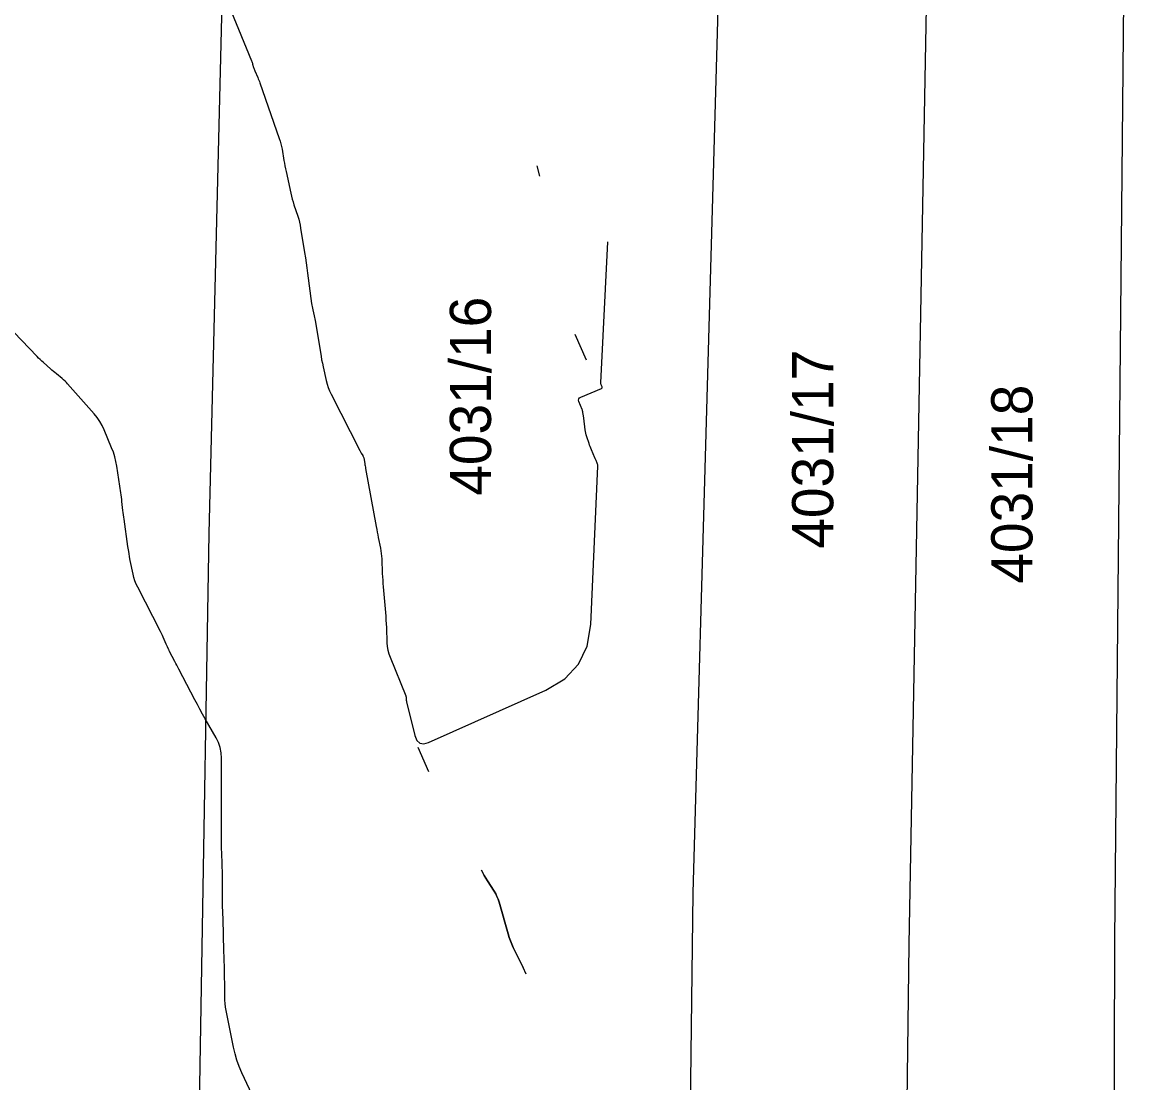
# Model space of a CAD drawing. Extents: x -534410 to -534262, y -1190162 to -1189584.
# Drawn here: x -534348.63 to -534325.54, y -1189747.77 to -1189725.88 of the extents above; entities that cross this region are included whole.
import ezdxf

# ---------------------------------------------------------------- set-up
doc = ezdxf.new("R2010")
doc.units = 0
for name, color, linetype in [('30', 7, 'Continuous'), ('31', 7, 'Continuous'), ('Hranice parcel', 7, 'Continuous'), ('Parcelní čísla', 7, 'Continuous')]:
    doc.layers.add(name, color=color, linetype=linetype)

msp = doc.modelspace()

# ---------------------------------------------------------------- linework, layer by layer
at = {"layer": '30'}
for points in [[(-534338.004, -1189728.845), (-534337.953, -1189729.054)], [(-534343.782, -1189748.239), (-534344.094, -1189747.565), (-534344.149, -1189747.437), (-534344.196, -1189747.307), (-534344.235, -1189747.175), (-534344.266, -1189747.039), (-534344.42, -1189746.283), (-534344.433, -1189746.21), (-534344.442, -1189746.138), (-534344.447, -1189746.065), (-534344.449, -1189745.992), (-534344.449, -1189745.698), (-534344.45, -1189745.624), (-534344.45, -1189745.551), (-534344.452, -1189745.477), (-534344.454, -1189745.404), (-534344.467, -1189745.021), (-534344.469, -1189744.933), (-534344.472, -1189744.844), (-534344.475, -1189744.756), (-534344.477, -1189744.668), (-534344.49, -1189744.219), (-534344.492, -1189744.156), (-534344.493, -1189744.094), (-534344.493, -1189744.032), (-534344.494, -1189743.969), (-534344.494, -1189743.72), (-534344.494, -1189743.657), (-534344.495, -1189743.595), (-534344.496, -1189743.533), (-534344.497, -1189743.47), (-534344.51, -1189743.032), (-534344.513, -1189742.938), (-534344.515, -1189742.844), (-534344.516, -1189742.751), (-534344.516, -1189742.657), (-534344.516, -1189741.069), (-534344.523, -1189740.959), (-534344.544, -1189740.852), (-534344.579, -1189740.749), (-534344.628, -1189740.649), (-534344.851, -1189740.259), (-534344.906, -1189740.161), (-534344.96, -1189740.063), (-534345.013, -1189739.964), (-534345.066, -1189739.864), (-534345.394, -1189739.231), (-534345.414, -1189739.192), (-534345.435, -1189739.153), (-534345.455, -1189739.115), (-534345.476, -1189739.076), (-534345.587, -1189738.868), (-534345.593, -1189738.856), (-534345.599, -1189738.844), (-534345.605, -1189738.832), (-534345.611, -1189738.82), (-534345.633, -1189738.771), (-534345.639, -1189738.758), (-534345.644, -1189738.746), (-534345.65, -1189738.734), (-534345.655, -1189738.721), (-534345.718, -1189738.571), (-534345.731, -1189738.542), (-534345.744, -1189738.513), (-534345.758, -1189738.485), (-534345.772, -1189738.457), (-534346.245, -1189737.541), (-534346.276, -1189737.476), (-534346.302, -1189737.409), (-534346.323, -1189737.341), (-534346.34, -1189737.271), (-534346.399, -1189736.987), (-534346.413, -1189736.915), (-534346.425, -1189736.844), (-534346.437, -1189736.773), (-534346.448, -1189736.701), (-534346.527, -1189736.139), (-534346.533, -1189736.094), (-534346.539, -1189736.048), (-534346.545, -1189736.002), (-534346.55, -1189735.957), (-534346.571, -1189735.774), (-534346.576, -1189735.728), (-534346.582, -1189735.683), (-534346.588, -1189735.637), (-534346.595, -1189735.591), (-534346.677, -1189735.041), (-534346.695, -1189734.943), (-534346.718, -1189734.848), (-534346.747, -1189734.754), (-534346.783, -1189734.661), (-534346.935, -1189734.295), (-534346.976, -1189734.206), (-534347.024, -1189734.121), (-534347.08, -1189734.04), (-534347.142, -1189733.963), (-534347.692, -1189733.341), (-534347.718, -1189733.312), (-534347.745, -1189733.285), (-534347.774, -1189733.259), (-534347.804, -1189733.234), (-534347.925, -1189733.136), (-534347.956, -1189733.112), (-534347.985, -1189733.087), (-534348.015, -1189733.061), (-534348.044, -1189733.036), (-534348.191, -1189732.905), (-534348.225, -1189732.875), (-534348.259, -1189732.843), (-534348.291, -1189732.811), (-534348.323, -1189732.778), (-534348.801, -1189732.273)], [(-534337.218, -1189732.319), (-534336.987, -1189732.845)]]:
    msp.add_lwpolyline(points, dxfattribs=at)
at = {"layer": '31'}
for points in [[(-534344.323, -1189725.638), (-534343.896, -1189726.672), (-534343.889, -1189726.689), (-534343.883, -1189726.706), (-534343.877, -1189726.723), (-534343.872, -1189726.74), (-534343.853, -1189726.81), (-534343.848, -1189726.827), (-534343.842, -1189726.844), (-534343.835, -1189726.861), (-534343.829, -1189726.878), (-534343.768, -1189727.016), (-534343.756, -1189727.044), (-534343.744, -1189727.073), (-534343.733, -1189727.102), (-534343.723, -1189727.131), (-534343.323, -1189728.277), (-534343.305, -1189728.332), (-534343.29, -1189728.388), (-534343.277, -1189728.444), (-534343.266, -1189728.501), (-534343.226, -1189728.73), (-534343.216, -1189728.787), (-534343.206, -1189728.844), (-534343.194, -1189728.901), (-534343.182, -1189728.958), (-534343.085, -1189729.408), (-534343.071, -1189729.468), (-534343.055, -1189729.529), (-534343.038, -1189729.588), (-534343.019, -1189729.648), (-534342.94, -1189729.884), (-534342.922, -1189729.944), (-534342.906, -1189730.004), (-534342.892, -1189730.064), (-534342.881, -1189730.126), (-534342.799, -1189730.634), (-534342.783, -1189730.739), (-534342.767, -1189730.845), (-534342.752, -1189730.95), (-534342.738, -1189731.056), (-534342.656, -1189731.685), (-534342.652, -1189731.717), (-534342.646, -1189731.749), (-534342.64, -1189731.781), (-534342.632, -1189731.813), (-534342.601, -1189731.939), (-534342.593, -1189731.971), (-534342.586, -1189732.003), (-534342.58, -1189732.035), (-534342.575, -1189732.067), (-534342.474, -1189732.698), (-534342.461, -1189732.771), (-534342.448, -1189732.844), (-534342.433, -1189732.917), (-534342.418, -1189732.989), (-534342.353, -1189733.277), (-534342.334, -1189733.349), (-534342.312, -1189733.418), (-534342.284, -1189733.487), (-534342.253, -1189733.553), (-534341.658, -1189734.721), (-534341.651, -1189734.733), (-534341.645, -1189734.746), (-534341.637, -1189734.759), (-534341.63, -1189734.771), (-534341.6, -1189734.82), (-534341.594, -1189734.832), (-534341.588, -1189734.845), (-534341.583, -1189734.859), (-534341.58, -1189734.873), (-534341.558, -1189734.991), (-534341.553, -1189735.015), (-534341.548, -1189735.039), (-534341.544, -1189735.064), (-534341.539, -1189735.088), (-534341.321, -1189736.291), (-534341.311, -1189736.347), (-534341.3, -1189736.402), (-534341.29, -1189736.457), (-534341.279, -1189736.513), (-534341.235, -1189736.734), (-534341.225, -1189736.789), (-534341.218, -1189736.845), (-534341.212, -1189736.901), (-534341.208, -1189736.957), (-534341.195, -1189737.26), (-534341.191, -1189737.33), (-534341.187, -1189737.399), (-534341.182, -1189737.468), (-534341.177, -1189737.537), (-534341.132, -1189738.064), (-534341.126, -1189738.142), (-534341.12, -1189738.22), (-534341.116, -1189738.298), (-534341.112, -1189738.376), (-534341.099, -1189738.688), (-534341.093, -1189738.766), (-534341.08, -1189738.842), (-534341.06, -1189738.916), (-534341.034, -1189738.989), (-534340.712, -1189739.786), (-534340.709, -1189739.796), (-534340.706, -1189739.806), (-534340.704, -1189739.816), (-534340.703, -1189739.826), (-534340.7, -1189739.868), (-534340.7, -1189739.878), (-534340.698, -1189739.888), (-534340.696, -1189739.898), (-534340.694, -1189739.909), (-534340.523, -1189740.605), (-534340.483, -1189740.704), (-534340.423, -1189740.76), (-534340.341, -1189740.773), (-534340.239, -1189740.745), (-534337.816, -1189739.668), (-534337.427, -1189739.436), (-534337.143, -1189739.132), (-534336.964, -1189738.757), (-534336.89, -1189738.311), (-534336.745, -1189735.042), (-534336.745, -1189735.027), (-534336.747, -1189735.012), (-534336.751, -1189734.998), (-534336.757, -1189734.984), (-534336.782, -1189734.929), (-534336.788, -1189734.915), (-534336.794, -1189734.901), (-534336.8, -1189734.888), (-534336.806, -1189734.874), (-534336.877, -1189734.706), (-534336.89, -1189734.673), (-534336.903, -1189734.64), (-534336.915, -1189734.607), (-534336.927, -1189734.573), (-534336.973, -1189734.434), (-534336.984, -1189734.399), (-534336.993, -1189734.364), (-534337, -1189734.329), (-534337.006, -1189734.293), (-534337.038, -1189734.055), (-534337.045, -1189734.004), (-534337.054, -1189733.936), (-534337.057, -1189733.919), (-534337.061, -1189733.903), (-534337.065, -1189733.887), (-534337.071, -1189733.87), (-534337.135, -1189733.711), (-534337.142, -1189733.681), (-534337.138, -1189733.656), (-534337.123, -1189733.635), (-534337.097, -1189733.62), (-534336.669, -1189733.438), (-534336.66, -1189733.432), (-534336.655, -1189733.426), (-534336.654, -1189733.417), (-534336.657, -1189733.408), (-534336.676, -1189733.365), (-534336.68, -1189733.355), (-534336.682, -1189733.344), (-534336.684, -1189733.333), (-534336.684, -1189733.321), (-534336.539, -1189730.411)], [(-534340.464, -1189740.845), (-534340.243, -1189741.344)], [(-534338.223, -1189745.528), (-534338.29, -1189745.392)]]:
    msp.add_lwpolyline(points, dxfattribs=at)
msp.add_lwpolyline([(-534338.491, -1189744.981), (-534338.523, -1189744.912), (-534338.551, -1189744.842), (-534338.577, -1189744.771), (-534338.599, -1189744.698), (-534338.785, -1189744.042), (-534338.804, -1189743.982), (-534338.828, -1189743.924), (-534338.855, -1189743.869), (-534338.887, -1189743.815), (-534339.023, -1189743.602), (-534339.057, -1189743.549), (-534339.089, -1189743.494), (-534339.119, -1189743.439), (-534339.148, -1189743.383), (-534339.119, -1189743.439), (-534339.089, -1189743.494), (-534339.057, -1189743.549), (-534339.023, -1189743.602), (-534338.887, -1189743.815), (-534338.855, -1189743.869), (-534338.828, -1189743.924), (-534338.804, -1189743.982), (-534338.785, -1189744.042), (-534338.599, -1189744.698), (-534338.577, -1189744.771), (-534338.551, -1189744.842), (-534338.523, -1189744.912), (-534338.491, -1189744.981), (-534338.29, -1189745.392)], close=True, dxfattribs=at)
at = {"layer": 'Hranice parcel'}
for points in [[(-534347.07, -1189935.15), (-534347.12, -1189900.1), (-534346.3, -1189826.77), (-534344.77, -1189736.43), (-534342.85, -1189658.07), (-534338.334, -1189584.47)], [(-534338.84, -1189942.48), (-534336.49, -1189881.83), (-534334.78, -1189743.85), (-534331.25, -1189619.05), (-534329.563, -1189584.47)], [(-534334.89, -1189942.46), (-534332.03, -1189880.06), (-534330.32, -1189744.92), (-534329.292, -1189689.47)], [(-534330.63, -1189942.43), (-534326.4, -1189862.47), (-534326.07, -1189744.82), (-534325.539, -1189689.47)]]:
    msp.add_lwpolyline(points, dxfattribs=at)

# ---------------------------------------------------------------- texts
at = {"layer": 'Parcelní čísla'}
for s, p in [('4031/16', (-534338.951, -1189735.653)), ('4031/17', (-534331.885, -1189736.747)), ('4031/18', (-534327.773, -1189737.469))]:
    msp.add_text(s, height=0.85, rotation=90, dxfattribs=at).set_placement(p)

doc.saveas('drawing.dxf')
